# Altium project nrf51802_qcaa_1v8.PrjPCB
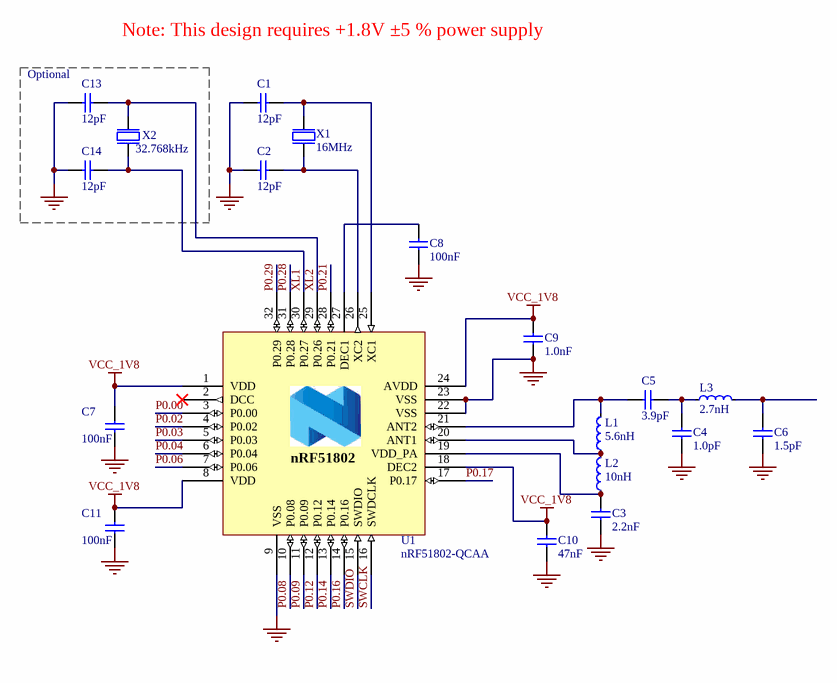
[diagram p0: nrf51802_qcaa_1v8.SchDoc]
1 sheet, 19 parts. Net scope: global (net labels, ports and power ports of the same name join across sheets).
Board file: nrf51802_qcaa_1v8.PcbDoc

## Sheet nrf51802_qcaa_1v8.SchDoc: nRF51802-QCAA Reference Layout (1.8V supply)
size A4; Revision: 1.0; SheetNumber: 1; SheetTotal: 1; DrawnBy: RUBR; DocumentSize: A4; PCAName: nRF51802-QCAA Reference Layout (1.8V supply)

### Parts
C1  12pF  [CAPC1005X04L]
C2  12pF  [CAPC1005X04L]
C3  2.2nF  [CAPC1005X04L]
C4  1.0pF  [CAPC1005X04L]
C5  3.9pF  [CAPC1005X04L]
C6  1.5pF  [CAPC1005X04L]
C7  100nF  [CAPC1005X04L]
C8  100nF  [CAPC1005X04L]
C9  1.0nF  [CAPC1005X04L]
C10  47nF  [CAPC1005X04L]
C11  100nF  [CAPC1005X04L]
C13  12pF  [CAPC1005X04L]
C14  12pF  [CAPC1005X04L]
L1  5.6nH  [INDC1005X04L]
L2  10nH  [INDC1005X04L]
L3  2.7nH  [INDC1005X04L]
U1  nRF51802-QCAA  [Nordic_QFN50P500X500X90-33N]
X1  16MHz  [BT-XTAL_2520]
X2  32.768kHz  [XTAL_3215]

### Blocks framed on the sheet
Optional: C13 C14 X2

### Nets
GND: C1.2 C2.2 C3.2 C4.2 C6.2 C7.2 C8.2 C9.2 C10.2 C11.2 C13.1 C14.1 U1.9(VSS) U1.22(VSS) U1.23(VSS) U1.33 X1.2(GND) X1.4(GND)
VCC_1V8: C7.1 C9.1 C10.1 C11.1 U1.1(VDD) U1.8(VDD) U1.18(DEC2) U1.24(AVDD)
P0.00: U1.3(P0.00)
P0.02: U1.4(P0.02)
P0.03: U1.5(P0.03)
P0.04: U1.6(P0.04)
P0.06: U1.7(P0.06)
P0.08: U1.10(P0.08)
P0.09: U1.11(P0.09)
P0.12: U1.12(P0.12)
P0.14: U1.13(P0.14)
P0.16: U1.14(P0.16)
P0.17: U1.17(P0.17)
P0.21: U1.28(P0.21)
P0.28: U1.31(P0.28)
P0.29: U1.32(P0.29)
SWCLK: U1.16(SWDCLK)
SWDIO: U1.15(SWDIO)
XL1: C14.2 U1.30(P0.27) X2.2(out)
XL2: C13.2 U1.29(P0.26) X2.1(inp)
NetC1_1: C1.1 U1.25(XC1) X1.1(inp)
NetC2_1: C2.1 U1.26(XC2) X1.3(out)
NetC3_1: C3.1 L2.1 U1.19(VDD_PA)
NetC4_1: C4.1 C5.2 L3.1
NetC5_1: C5.1 L1.2 U1.21(ANT2)
NetC6_1: C6.1 L3.2
NetC8_1: C8.1 U1.27(DEC1)
NetL1_1: L1.1 L2.2 U1.20(ANT1)

Not connected (* = marked no-connect by the designer): U1 2(DCC)*

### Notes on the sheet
- Note: This design requires +1.8V ±5 % power supply

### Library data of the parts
C1 C2 C13 C14 = C0402-12p: Capacitor, NP0, ±2%; Note: 50V; Artikkelnr Noca: 20029159; Artikkelnr Simpro: N.A.
C3 = C0402-2n2: Capacitor, X7R, ±10%; Note: 50V; Artikkelnr Noca: 20039221; Artikkelnr Simpro: N.A.
C4 = C0402-1.0p: Capacitor, NP0, ±0.1pF; Note: 50V; Artikkelnr Noca: 20029140; Artikkelnr Simpro: N.A.
C5 = C0402-3.9p: Capacitor, NP0, ±0.1pF; Note: 50V; Artikkelnr Noca: N.A.
C6 = C0402-1.5p: Capacitor, NP0, ±0.1pF; Note: 50V; Artikkelnr Noca: 20029139; Artikkelnr Simpro: N.A.
C7 C8 C11 = C0402-100n: Capacitor, X7R, ±10%; Note: 16V; Artikkelnr Noca: 20039200; Artikkelnr Simpro: N.A.
C9 = C0402-1n0: Capacitor, X7R, ±10%; Note: 50V; Artikkelnr Noca: 20039223; Artikkelnr Simpro: N.A.
C10 = C0402-47n: Capacitor, X7R, ±10%; Note: Chip Cap 10%; Artikkelnr Noca: 20039389; Artikkelnr Simpro: N.A.
L1 = L0402-5n6: High frequency chip inductor ±5%; Manufacturer: Murata; Manufacturer Part Number: LQP15MN5N6B02D; Artikkelnr Noca: 33029161; Artikkelnr Simpro: N.A.
L2 = L0402-10n: High frequency chip inductor ±5%; Manufacturer: Murata; Manufacturer Part Number: LQP15MN10NG02D; Artikkelnr Noca: 33029425; Artikkelnr Simpro: N.A.
L3 = L0402-2n7: High frequency chip inductor ±5%; Manufacturer: Murata; Manufacturer Part Number: LQP15MN2N7B02D; Artikkelnr Noca: 33029150; Artikkelnr Simpro: N.A.
U1 = nRF51802-QCAA: Multi-protocol Bluetooth Low Energy and 2.4GHz proprietary system-on-chip; Manufacturer: Nordic Semiconductor; Note: nRF51802 - QFN32 5x5 0.5mm pitch; Artikkelnr Noca: N.A.
X1 = XTAL_SMD2520_16MHz_8pF_NDK: XTAL SMD 2520, 16MHz, 8pF, ±40ppm; Manufacturer: NDK; Manufacturer Part Number: NX2520SA/16MHz/EXS00A-CS06713; Note: XTAL SMD 16.000MHz; Artikkelnr Noca: 22019192; Artikkelnr Simpro: N.A.
X2 = XTAL_FC-135 32.768k: XTAL SMD 3215, 32.768kHz, 9pF, ±20ppm; Manufacturer: Epson Toyocom; Manufacturer Part Number: FC-135 32.768KHZ ±20PPM,9.0PF; 2nd source part number: 127-8037; Note: XTAL SMD 32.768kHz, 3215; Artikkelnr Noca: 22019091; Artikkelnr Simpro: N.A.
